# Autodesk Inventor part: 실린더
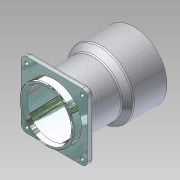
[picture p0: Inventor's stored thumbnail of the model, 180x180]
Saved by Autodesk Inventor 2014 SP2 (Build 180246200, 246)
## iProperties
Manager: KYOUNG IL JANG
Company: 한국ATC센터
Created: 2012-10
Part Number: 실린더
Material: 일반
Document SubType Name: 모델링
Density: 1 g/cm^3
Checked By: KYOUNG IL JANG
Vendor: CBT Solutions
Designer: KYOUNG IL JANG
Appearance: _시험_알루미늄 표면거칠기
Author: KYOUNG IL JANG
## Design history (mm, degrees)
sketch "스케치1"
  geometry: L1 (0, 0)-(0, 112); L2 (30, 0)-(30, 112); L3 (30, 112)-(42.5, 112); L4 (42.5, 112)-(42.5, 69); L5 (42.5, 69)-(35, 61); L6 (35, 61)-(35, 0); L7 (35, 0)-(30, 0)
  constraints: 14 end point, 4 parallel, 2 point on line, 1 perpendicular, 1 vertical
  dimensions: "d0" = 112 distance of L1.start L1.end; "d2" = 85 diameter of L4 L1; "d3" = 70 diameter of L6 L1; "d5" = 60 diameter of L2 L1; "d33" = 43 distance of L3.end L4.end; "d34" = 51 distance from line of L3 L5.end
revolve "회전1" stored, may be unused: angle "d6" = 90 deg
node "작업 평면1"
sketch "스케치2"
  geometry: L1 (-42.5, 42.5)-(42.5, 42.5); L2 (42.5, 42.5)-(42.5, -42.5); L3 (42.5, -42.5)-(-42.5, -42.5); L4 (-42.5, -42.5)-(-42.5, 42.5); C1 r 35 at (0, 0) reference; 3 further points
  constraints: 8 end point, 2 midpoint, 2 parallel, 2 perpendicular, 1 horizontal, 1 horizontal alignment, 1 vertical alignment
  dimensions: "d8" = 85 distance of L1.end L2.end
extrude "돌출1" join sketch "스케치2" distance "d9" = 8; taper "d10" = 0 deg
fillet "모깎기1" dims "d11" = 7, "d12" = 3
sketch "스케치3"
  geometry: L1 (0, 42.5)-(0, 30); 4 further points
  constraints: 2 end point, 2 vertical alignment, 1 midpoint, 1 point on line, 1 vertical, 2 other
hole "구멍1" sketch "스케치3" at (0, 36.25) diameter "d14" = 4.134; stored, may be unused: countersink angle "d18" = 90 deg, drill point angle "d20" = 118 deg; dims "d15" = 12, "d16" = 4, "d17" = 2, "d19" = 15
sketch "스케치4"
  geometry: C1 r 1.621 at (35.5, -35.5) reference; C2 r 1.621 at (35.5, 35.5) reference; C3 r 1.621 at (-35.5, -35.5) reference; C4 r 1.621 at (-35.5, 35.5) reference; 1 further point
hole "구멍2" sketch "스케치4" at (35.5, 35.5), (35.5, -35.5), (-35.5, -35.5), (-35.5, 35.5) diameter "d26" = 4.5; stored, may be unused: countersink angle "d30" = 90 deg, drill point angle "d32" = 118 deg; dims "d27" = 12, "d28" = 8, "d29" = 4.4, "d31" = 15
chamfer "모따기1" distance "d35" = 5; stored, may be unused: second distance "d36" = 2, angle "d37" = 20 deg
chamfer "모따기2" distance "d38" = 1; stored, may be unused: second distance "d39" = 2, angle "d40" = 20 deg
node "솔리드1"
pattern_circular "원형 패턴1" dims angle "d22" = 360 deg
node "참조1"
node "참조2"
node "참조3"
node "참조4"
other parameters: "KFactor" = 4.4
